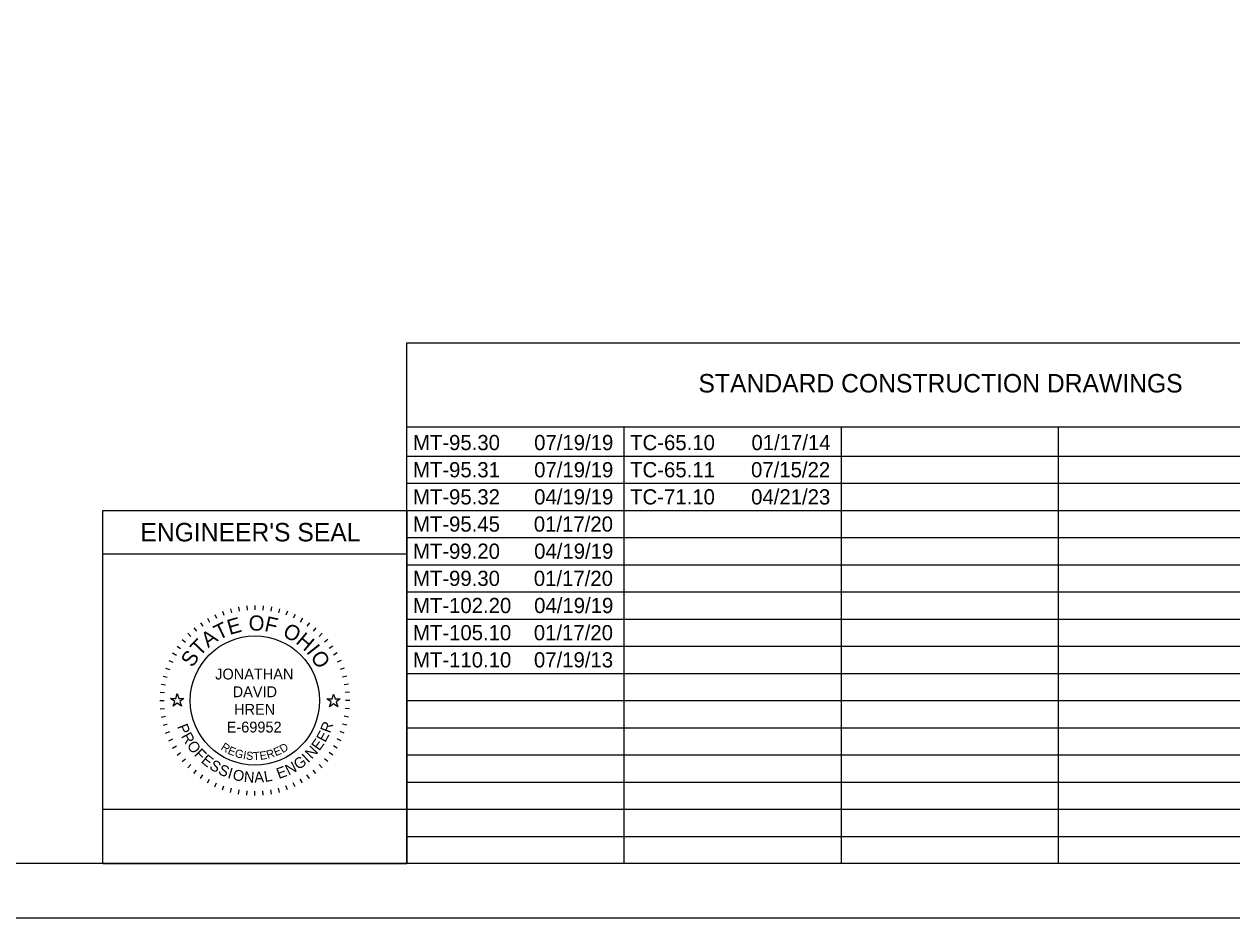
# Model space of a CAD drawing. Extents: x -10 to 89.7, y -4.8 to 22.
# Drawn here: x 7.72 to 18.85, y 0 to 8.23 of the extents above; entities that cross this region are included whole.
import ezdxf

# ---------------------------------------------------------------- set-up
doc = ezdxf.new("R2010")
doc.units = 0
for name, color, linetype in [('GM_X_Minor_Lake', 7, 'Continuous'), ('GM_X_Minor_River', 7, 'Continuous'), ('GM_X_Minor_River_Text', 7, 'Continuous'), ('SH_Text', 7, 'Continuous')]:
    doc.layers.add(name, color=color, linetype=linetype)

msp = doc.modelspace()

# ---------------------------------------------------------------- linework, layer by layer
at = {"layer": 'GM_X_Minor_Lake'}
for p, q in [((11.25, 5.292), (24.7, 5.292)), ((11.25, 0.5), (11.25, 5.292)), ((11.25, 4.521), (24.7, 4.521)), ((13.25, 0.5), (13.25, 4.521)), ((15.25, 0.5), (15.25, 4.521)), ((17.25, 0.5), (17.25, 4.521)), ((11.25, 4.25), (24.7, 4.25)), ((11.25, 4), (24.7, 4)), ((8.45, 0.5), (8.45, 3.75)), ((8.45, 3.75), (11.25, 3.75)), ((11.25, 3.75), (24.7, 3.75)), ((11.25, 3.75), (11.25, 0.5)), ((11.25, 3.5), (24.7, 3.5)), ((8.45, 3.35), (11.25, 3.35)), ((11.25, 3.25), (24.7, 3.25)), ((11.25, 3), (24.7, 3)), ((9.48, 2.793), (9.497, 2.757)), ((9.551, 2.822), (9.564, 2.785)), ((9.624, 2.845), (9.634, 2.807)), ((9.698, 2.862), (9.705, 2.822)), ((9.774, 2.872), (9.777, 2.832)), ((9.85, 2.875), (9.85, 2.835)), ((9.926, 2.872), (9.923, 2.832)), ((10.002, 2.862), (9.995, 2.822)), ((10.076, 2.845), (10.066, 2.807)), ((10.149, 2.822), (10.136, 2.785)), ((10.22, 2.793), (10.203, 2.757)), ((9.288, 2.67), (9.313, 2.64)), ((9.348, 2.717), (9.371, 2.684)), ((9.413, 2.758), (9.433, 2.723)), ((10.287, 2.758), (10.267, 2.723)), ((10.352, 2.717), (10.329, 2.684)), ((10.412, 2.67), (10.387, 2.64)), ((11.25, 2.75), (24.7, 2.75)), ((9.18, 2.562), (9.21, 2.537)), ((9.231, 2.619), (9.26, 2.59)), ((10.469, 2.619), (10.44, 2.59)), ((10.52, 2.562), (10.49, 2.537)), ((9.133, 2.502), (9.166, 2.479)), ((10.567, 2.502), (10.534, 2.479)), ((11.25, 2.5), (24.7, 2.5)), ((9.057, 2.37), (9.093, 2.353)), ((9.092, 2.438), (9.127, 2.418)), ((10.608, 2.438), (10.573, 2.418)), ((10.643, 2.37), (10.607, 2.353)), ((9.005, 2.226), (9.043, 2.216)), ((9.028, 2.299), (9.065, 2.286)), ((10.672, 2.299), (10.635, 2.286)), ((10.695, 2.226), (10.657, 2.216)), ((11.25, 2.25), (24.7, 2.25)), ((8.988, 2.152), (9.028, 2.145)), ((10.712, 2.152), (10.672, 2.145)), ((8.978, 2.076), (9.018, 2.073)), ((10.722, 2.076), (10.682, 2.073)), ((8.975, 2), (9.015, 2)), ((8.978, 1.924), (9.018, 1.927)), ((10.722, 1.924), (10.682, 1.927)), ((10.725, 2), (10.685, 2)), ((11.25, 2), (24.7, 2)), ((8.988, 1.848), (9.028, 1.855)), ((9.005, 1.774), (9.043, 1.784)), ((10.695, 1.774), (10.657, 1.784)), ((10.712, 1.848), (10.672, 1.855)), ((9.028, 1.701), (9.065, 1.714)), ((10.672, 1.701), (10.635, 1.714)), ((11.25, 1.75), (24.7, 1.75)), ((9.057, 1.63), (9.093, 1.647)), ((9.092, 1.563), (9.127, 1.583)), ((10.608, 1.563), (10.573, 1.583)), ((10.643, 1.63), (10.607, 1.647)), ((9.133, 1.498), (9.166, 1.521)), ((9.18, 1.438), (9.21, 1.463)), ((10.52, 1.438), (10.49, 1.463)), ((10.567, 1.498), (10.534, 1.521)), ((11.25, 1.5), (24.7, 1.5)), ((9.231, 1.381), (9.26, 1.41)), ((9.288, 1.33), (9.313, 1.36)), ((10.412, 1.33), (10.387, 1.36)), ((10.469, 1.381), (10.44, 1.41)), ((9.348, 1.283), (9.371, 1.316)), ((9.413, 1.242), (9.433, 1.277)), ((9.48, 1.207), (9.497, 1.243)), ((10.22, 1.207), (10.203, 1.243)), ((10.287, 1.242), (10.267, 1.277)), ((10.352, 1.283), (10.329, 1.316)), ((11.25, 1.25), (24.7, 1.25)), ((9.551, 1.178), (9.564, 1.215)), ((9.624, 1.155), (9.634, 1.193)), ((9.698, 1.138), (9.705, 1.178)), ((9.774, 1.128), (9.777, 1.168)), ((9.85, 1.125), (9.85, 1.165)), ((9.926, 1.128), (9.923, 1.168)), ((10.002, 1.138), (9.995, 1.178)), ((10.076, 1.155), (10.066, 1.193)), ((10.149, 1.178), (10.136, 1.215)), ((11.25, 1), (24.7, 1)), ((11.25, 0.75), (24.7, 0.75)), ((8.45, 0.5), (11.25, 0.5))]:
    msp.add_line(p, q, dxfattribs=at)
for points in [[(9.074, 2.02), (9.121, 2.02), (9.135, 2.065), (9.149, 2.02), (9.196, 2.02), (9.158, 1.992), (9.173, 1.948), (9.135, 1.975), (9.097, 1.948), (9.112, 1.992)], [(10.513, 2.015), (10.56, 2.015), (10.574, 2.059), (10.589, 2.015), (10.635, 2.015), (10.598, 1.987), (10.612, 1.942), (10.574, 1.97), (10.536, 1.942), (10.551, 1.987)], [(8.45, 0.5), (8.45, 1), (11.25, 1), (11.25, 0.5)]]:
    msp.add_lwpolyline(points, close=True, dxfattribs=at)
msp.add_circle((9.85, 2), 0.595, dxfattribs=at)
at = {"layer": 'GM_X_Minor_River'}
msp.add_lwpolyline([(1.5, 21.5), (33.5, 21.5), (33.5, 0.5), (1.5, 0.5)], close=True, dxfattribs=at)
at = {"layer": 'SH_Text'}
msp.add_lwpolyline([(0, 0), (34, 0), (34, 22), (0, 22)], close=True, dxfattribs=at)

# ---------------------------------------------------------------- texts
at = {"layer": 'GM_X_Minor_Lake'}
for s, height, p in [("ENGINEER'S SEAL", 0.17, (8.795, 3.465)), ('JONATHAN', 0.1, (9.484, 2.194)), ('DAVID', 0.1, (9.645, 2.031)), ('HREN', 0.1, (9.658, 1.869)), ('E-69952', 0.1, (9.59, 1.706))]:
    msp.add_text(s, height=height, dxfattribs=at).set_placement(p)
for s, height, rotation, p in [('O', 0.14, 359.7812, (9.792, 2.644)), ('T', 0.14, 25.7167, (9.516, 2.554)), ('E', 0.14, 15.7571, (9.617, 2.603)), ('F', 0.14, 347.4362, (9.931, 2.642)), ('O', 0.14, 332.2586, (10.096, 2.598)), ('T', 0.14, 46.4344, (9.342, 2.4)), ('A', 0.14, 36.4747, (9.419, 2.482)), ('H', 0.14, 319.9136, (10.218, 2.532)), ('S', 0.14, 57.1924, (9.276, 2.298)), ('I', 0.14, 308.367, (10.317, 2.447)), ('O', 0.14, 303.1491, (10.356, 2.403)), ('P', 0.1, 291.494, (9.132, 1.762)), ('R', 0.1, 69.2322, (10.541, 1.694)), ('R', 0.1, 298.7311, (9.168, 1.673)), ('E', 0.1, 61.9951, (10.497, 1.609)), ('O', 0.1, 306.4666, (9.218, 1.585)), ('F', 0.1, 314.7068, (9.284, 1.498)), ('R', 0.075, 327.8239, (9.53, 1.554)), ('E', 0.075, 337.7777, (9.594, 1.513)), ('E', 0.075, 23.3052, (10.041, 1.486)), ('D', 0.075, 31.466, (10.105, 1.514)), ('N', 0.1, 47.0224, (10.374, 1.455)), ('E', 0.1, 54.758, (10.443, 1.531)), ('E', 0.1, 321.4393, (9.347, 1.435)), ('S', 0.1, 328.6764, (9.422, 1.377)), ('G', 0.075, 344.2727, (9.658, 1.485)), ('I', 0.075, 350.6464, (9.737, 1.463)), ('S', 0.075, 353.7858, (9.765, 1.458)), ('T', 0.075, 3.0061, (9.835, 1.451)), ('E', 0.075, 8.9826, (9.899, 1.453)), ('R', 0.075, 17.6836, (9.969, 1.463)), ('G', 0.1, 35.0469, (10.25, 1.358)), ('I', 0.1, 43.287, (10.338, 1.422)), ('S', 0.1, 335.9134, (9.504, 1.328)), ('I', 0.1, 343.1505, (9.592, 1.289)), ('O', 0.1, 346.8859, (9.638, 1.274)), ('N', 0.1, 355.1261, (9.745, 1.251)), ('A', 0.1, 2.8617, (9.846, 1.244)), ('L', 0.1, 10.0987, (9.942, 1.249)), ('E', 0.1, 20.0742, (10.07, 1.277)), ('N', 0.1, 27.3113, (10.16, 1.31))]:
    msp.add_text(s, height=height, rotation=rotation, dxfattribs=at).set_placement(p)
at = {"layer": 'GM_X_Minor_River_Text'}
for s, height, p in [('STANDARD CONSTRUCTION DRAWINGS', 0.17, (13.934, 4.836)), ('07/19/19', 0.14, (12.421, 4.305)), ('01/17/14', 0.14, (14.422, 4.305)), ('MT-95.30', 0.14, (11.305, 4.305)), ('TC-65.10', 0.14, (13.305, 4.305)), ('MT-95.31', 0.14, (11.305, 4.055)), ('07/19/19', 0.14, (12.421, 4.055)), ('TC-65.11', 0.14, (13.305, 4.055)), ('07/15/22', 0.14, (14.418, 4.055)), ('MT-95.32', 0.14, (11.305, 3.805)), ('04/19/19', 0.14, (12.421, 3.805)), ('TC-71.10', 0.14, (13.305, 3.805)), ('04/21/23', 0.14, (14.419, 3.805)), ('MT-95.45', 0.14, (11.305, 3.555)), ('01/17/20', 0.14, (12.418, 3.555)), ('04/19/19', 0.14, (12.421, 3.305)), ('MT-99.20', 0.14, (11.305, 3.305)), ('MT-99.30', 0.14, (11.305, 3.055)), ('01/17/20', 0.14, (12.418, 3.055)), ('MT-102.20', 0.14, (11.305, 2.805)), ('04/19/19', 0.14, (12.421, 2.805)), ('MT-105.10', 0.14, (11.305, 2.555)), ('01/17/20', 0.14, (12.418, 2.555)), ('MT-110.10', 0.14, (11.305, 2.305)), ('07/19/13', 0.14, (12.419, 2.305))]:
    msp.add_text(s, height=height, dxfattribs=at).set_placement(p)

doc.saveas('drawing.dxf')
